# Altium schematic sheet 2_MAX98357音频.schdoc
size 431 x 309 mm; Symbol: Sheet-Symbol_A3; Device: Sheet-Symbol_A3; @Page Name: MAX98357音频; @Create Date: 2023-05-03; @Page Count: 4; @Page No: 2; @Project Name: 3.7寸墨水屏; @Schematic Name: Schematic1; @Update Date: 2023-06-01; Company: 嘉立创EDA; Page Size: A3; Version: V1.0
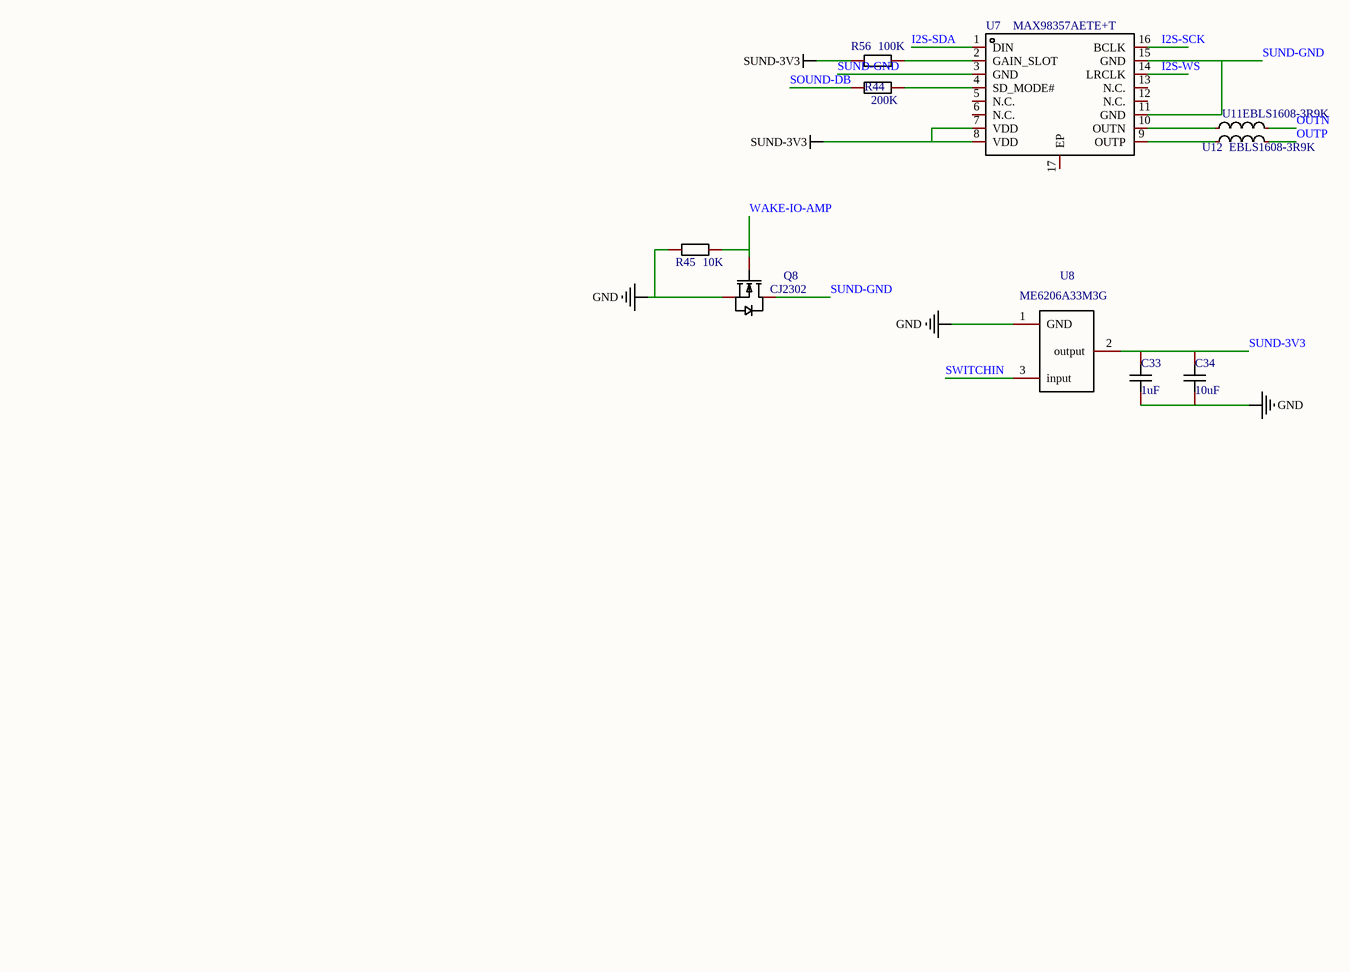
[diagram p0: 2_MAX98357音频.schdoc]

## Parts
C33  1uF  [C0603]
C34  10uF  [C0603]
Q8  CJ2302  [SOT-23-3_L2.9-W1.3-P1.90-LS2.4-BR]
R44  200K  [R0603]
R45  10K  [R0603]
R56  100K  [R0603]
U7  MAX98357AETE+T  [TQFN-16_L3.0-W3.0-P0.50-BL-EP1.5]
U8  ME6206A33M3G  [SOT-23-3_L2.9-W1.6-P1.90-LS2.8-BR]
U11  EBLS1608-3R9K  [L0603]
U12  EBLS1608-3R9K  [L0603]

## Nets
GND: C33.1 C34.1 Q8.2(S) R45.1 U8.1(GND)
SUND-3V3: C33.2 C34.2 R56.1 U7.7(VDD) U7.8(VDD) U8.2(output)
I2S-SCK: U7.16(BCLK)
I2S-SDA: U7.1(DIN)
I2S-WS: U7.14(LRCLK)
OUTN: U11.2
OUTP: U12.2
SOUND-DB: R44.1
SUND-GND: Q8.3(D) U7.3(GND) U7.11(GND) U7.15(GND)
SWITCHIN: U8.3(input)
WAKE-IO-AMP: Q8.1(G) R45.2
NetR44_2: R44.2 U7.4(SD_MODE#)
NetR56_2: R56.2 U7.2(GAIN_SLOT)
NetU7_9: U7.9(OUTP) U12.1
NetU7_10: U7.10(OUTN) U11.1

Not connected (* = marked no-connect by the designer): U7 5(N.C.) 6(N.C.) 12(N.C.) 13(N.C.) 17(EP)

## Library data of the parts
C33 C34 = CAP_0603: Symbol: CapAcitance; Convert to PCB: yes
Q8 = CJ2302: 类型:N沟道;漏源电压(Vdss):20V;连续漏极电流(Id):2.1A;功率(Pd):400mW;导通电阻(RDS(on)@Vgs,Id):35mΩ@4.5V,3.6A;阈值电压(Vgs(th)@Id):950mV@250uA;栅极电荷(Qg@Vgs):4nC@4.5V;输入电容(Ciss@Vds):300pF@10V;反向传输电容(Crss@Vds):80pF@10V;工作温度:-55℃~+150℃@(Tj);; Manufacturer: CJ(江苏长电/长晶); Add into BOM: yes; Type: N沟道; Drain Source Voltage (Vdss): 20V; Continuous Drain Current (Id): 2.1A; Power Dissipation (Pd): 400mW
R44 R45 R56 = Res_0603: Symbol: 电阻; Convert to PCB: yes
U7 = MAX98357AETE+T: 功放类型:-;输出功率:-;; Manufacturer: ADI(亚德诺)/MAXIM(美信); Add into BOM: yes
U8 = ME6206A33M3G: 输出类型:固定;输出极性:正;最大输入电压:6V;输出电压:3.3V;输出电流:300mA;电源纹波抑制比(PSRR):50dB@(1kHz);; Manufacturer: MICRONE(南京微盟); Add into BOM: yes; Output Type: 固定; Output Polarity: 正; Number of Outputs: 1; Maximum Input Voltage: 6V; Output Voltage: 3.3V; Dropout Voltage: 380mV@(200mA); Output Current: 300mA
U11 U12 = EBLS1608-3R9K: Add into BOM: yes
